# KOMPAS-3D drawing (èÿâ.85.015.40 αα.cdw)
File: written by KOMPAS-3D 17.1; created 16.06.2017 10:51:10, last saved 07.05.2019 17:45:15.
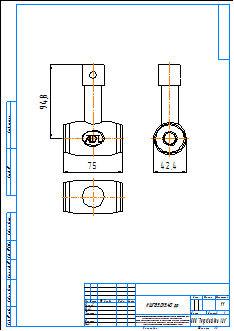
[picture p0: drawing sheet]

Sheet 1: A3, portrait

Title block, sheet 1: name: КШГ.85.015.40 рр; material: Внимание! Данный продукт является объектом авторского права ООО «Торговый Дом АДЛ». / Запрещается изменение, копирование, распространение / (в том числе путем копирования на другие сайты и ресурсы в Интернете) / или любое иное использование информации и объектов без предварительного / согласия правообладателя (ООО «Торговый Дом АДЛ»).; scale: 1:1; sheets: 1; organisation: ООО "Торговый дом АДЛ"; sheet format: A3; stored path: C:\Users\tra\Desktop\2д чертежи\Шаровые краны БИВАЛ\КШ_Бивал_серия_82_85\KOMPAS 2D\КШГ.85.015.40 рр.cdw

Views: Спереди 1, Проекционный вид 2, Проекционный вид 3
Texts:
  Klimkovich
  ADL
Dimensions and other numbers on the sheet: 75; 94,8; 42,4; 1:1; 1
